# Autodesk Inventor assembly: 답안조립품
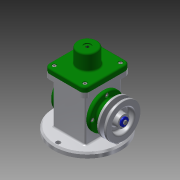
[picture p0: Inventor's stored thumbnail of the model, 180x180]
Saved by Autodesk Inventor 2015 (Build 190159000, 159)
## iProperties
Created: 2019-08
Part Number: 답안조립품
Document SubType Name: Assembly
Designer: now
Author: now
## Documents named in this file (18)
- C:\Users\now\Desktop\490804V1029\답안조립품.iam
- C:\Users\now\Desktop\490804V1029\E-링.ipt
- C:\Users\now\Desktop\490804V1029\V-벨트풀리.ipt
- C:\Users\now\Desktop\490804V1029\덮개.ipt
- C:\Users\now\Desktop\490804V1029\뒤커버.ipt
- C:\Users\now\Desktop\490804V1029\링크.ipt
- C:\Users\now\Desktop\490804V1029\베어링 17 x 40 x 12.ipt
- C:\Users\now\Desktop\490804V1029\본체.ipt
- C:\Users\now\Desktop\490804V1029\볼트 M4 x 8.ipt
- C:\Users\now\Desktop\490804V1029\볼트 M4 x 10.ipt
- C:\Users\now\Desktop\490804V1029\슬라이더.ipt
- C:\Users\now\Desktop\490804V1029\앞커버.ipt
- C:\Users\now\Desktop\490804V1029\오일 실 17 30 8.ipt
- C:\Users\now\Desktop\490804V1029\와셔 4x16.ipt
- C:\Users\now\Desktop\490804V1029\클레비스 핀 6 x 22.ipt
- 클레비스 핀 6 x 22.ipt
- C:\Users\now\Desktop\490804V1029\키 4 x 4 x 12.ipt
- C:\Users\now\Desktop\490804V1029\편심축.ipt
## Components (2 placed, 2 different names)
1. E-링:1
2. V-벨트풀리:1 — 각도:2
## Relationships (1: Angle 1)
- 각도:2 [Angle]: V-벨트풀리:1
